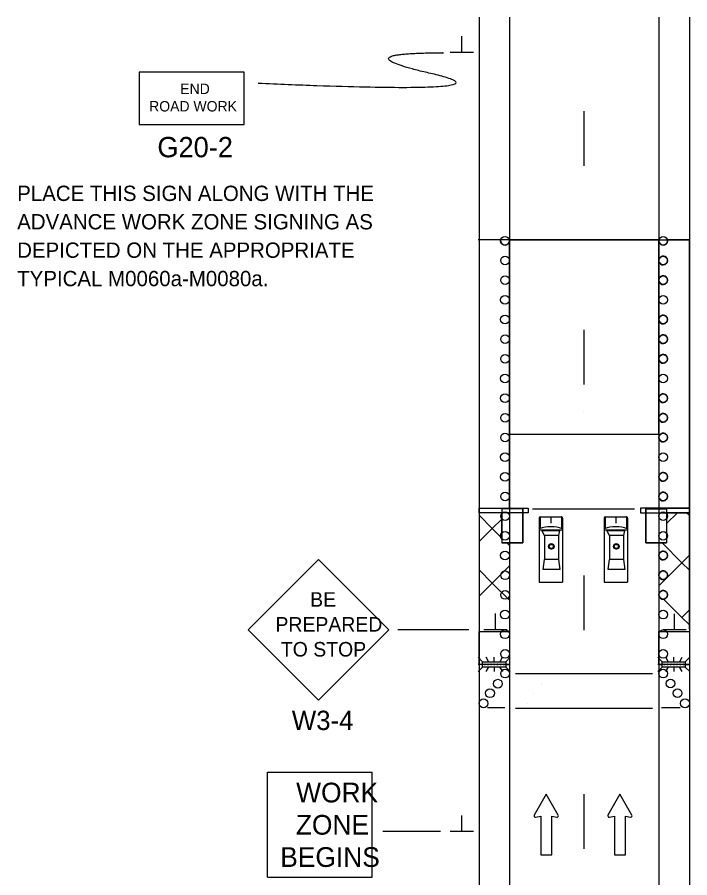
# Model space of a CAD drawing. Extents: x -1809 to 1554, y -1087 to 323.
# Drawn here: x -1702.2 to -1394.3, y -403.2 to -9.4 of the extents above; entities that cross this region are included whole.
import ezdxf

# ---------------------------------------------------------------- set-up
doc = ezdxf.new("R2010")
doc.units = 0
for name, color, linetype in [('BORDER', 7, 'Continuous'), ('BORDER_SIGNAL_WO', 7, 'Continuous'), ('Level 1', 7, 'Continuous'), ('Level 21', 7, 'Continuous'), ('Level 42', 7, 'Continuous'), ('MT_SCRATCH_LEVEL_A', 7, 'Continuous'), ('MT_SCRATCH_LEVEL_E', 7, 'Continuous'), ('MT_STAGE_1A_NOTES', 7, 'Continuous'), ('MT_STAGE_2A_NOTES', 7, 'Continuous'), ('PAVT_EDGE_EX', 7, 'Continuous'), ('PAVT_EDGE_PR', 7, 'Continuous'), ('TRAFFIC_SIGNS_PR', 7, 'Continuous'), ('TYPICAL_EX', 7, 'Continuous'), ('TYPICAL_TEXT_DIMEN_PR', 7, 'Continuous')]:
    doc.layers.add(name, color=color, linetype=linetype)

msp = doc.modelspace()

# ---------------------------------------------------------------- linework, layer by layer
at = {"layer": 'BORDER'}
msp.add_line((-1408.49, -9.43), (-1408.49, -689.95), dxfattribs=at)
at = {"layer": 'BORDER_SIGNAL_WO'}
for p, q in [((-1442.84, -52.45), (-1442.84, -77.45)), ((-1442.84, -152.45), (-1442.84, -177.45)), ((-1442.84, -264.95), (-1442.84, -289.95)), ((-1442.84, -364.95), (-1442.84, -389.95))]:
    msp.add_line(p, q, dxfattribs=at)
at = {"layer": 'Level 1'}
for p, q in [((-1463.23, -238.54), (-1463.23, -267.92)), ((-1462.87, -238.08), (-1462.73, -238.08)), ((-1462.81, -238.08), (-1453.23, -238.08)), ((-1453.23, -238.08), (-1453.09, -238.08)), ((-1453.11, -238.08), (-1453.09, -238.08)), ((-1452.6, -238.62), (-1452.6, -267.92)), ((-1433.49, -238.54), (-1433.49, -267.92)), ((-1433.13, -238.08), (-1432.99, -238.08)), ((-1433.07, -238.08), (-1423.48, -238.08)), ((-1423.48, -238.08), (-1423.34, -238.08)), ((-1423.36, -238.08), (-1423.35, -238.08)), ((-1422.85, -238.62), (-1422.85, -267.92)), ((-1462.1, -244.24), (-1453.92, -244.24)), ((-1460.87, -246.59), (-1462.1, -244.24)), ((-1454.39, -246.59), (-1460.87, -246.59)), ((-1460.87, -246.59), (-1460.87, -257.65)), ((-1453.92, -244.24), (-1454.39, -246.59)), ((-1454.39, -246.59), (-1454.39, -257.65)), ((-1432.35, -244.24), (-1424.17, -244.24)), ((-1431.13, -246.59), (-1432.35, -244.24)), ((-1424.64, -246.59), (-1431.13, -246.59)), ((-1431.13, -246.59), (-1431.13, -257.65)), ((-1424.17, -244.24), (-1424.64, -246.59)), ((-1424.64, -246.59), (-1424.64, -257.65)), ((-1461.44, -262.18), (-1460.87, -257.65)), ((-1454.39, -257.65), (-1460.87, -257.65)), ((-1454.39, -257.65), (-1453.82, -262.18)), ((-1431.69, -262.18), (-1431.13, -257.65)), ((-1424.64, -257.65), (-1431.13, -257.65)), ((-1424.64, -257.65), (-1424.08, -262.18)), ((-1453.82, -262.18), (-1461.44, -262.18)), ((-1424.08, -262.18), (-1431.69, -262.18)), ((-1463.23, -267.92), (-1452.6, -267.92)), ((-1433.49, -267.92), (-1422.85, -267.92))]:
    msp.add_line(p, q, dxfattribs=at)
at = {"layer": 'Level 21'}
msp.add_line((-1442.84, -189.95), (-1442.84, -189.95), dxfattribs=at)
at = {"layer": 'Level 42'}
for p, q in [((-1458.89, -309.8), (-1458.89, -309.8)), ((-1462.15, -314.41), (-1462.15, -314.41)), ((-1465.78, -318.79), (-1465.78, -318.79)), ((-1468.76, -323.4), (-1468.76, -323.4))]:
    msp.add_line(p, q, dxfattribs=at)
at = {"layer": 'MT_SCRATCH_LEVEL_A'}
for p, q in [((-1476.89, -9.43), (-1476.89, -689.95)), ((-1400.02, -236.15), (-1404.93, -241.06)), ((-1394.52, -237.51), (-1395.88, -236.15)), ((-1484.73, -243.37), (-1490.76, -237.33)), ((-1480.42, -239.06), (-1484.73, -243.37)), ((-1484.73, -243.37), (-1490.76, -249.4)), ((-1480.65, -247.44), (-1484.73, -243.37)), ((-1397.95, -259.08), (-1407.04, -249.99)), ((-1394.52, -255.65), (-1397.95, -259.08)), ((-1397.95, -259.08), (-1408.49, -269.63)), ((-1394.52, -262.51), (-1397.95, -259.08)), ((-1484.73, -268.37), (-1490.76, -262.33)), ((-1476.89, -260.53), (-1484.73, -268.37)), ((-1484.73, -268.37), (-1490.76, -274.4)), ((-1476.89, -276.2), (-1484.73, -268.37)), ((-1408.45, -273.58), (-1408.49, -273.54)), ((-1397.95, -284.08), (-1406.31, -275.72)), ((-1394.52, -280.65), (-1397.95, -284.08)), ((-1394.52, -287.51), (-1397.95, -284.08))]:
    msp.add_line(p, q, dxfattribs=at)
for points in [[(-1480.83, -111.25), (-1490.76, -111.25), (-1490.76, -234.05), (-1476.89, -234.05), (-1476.89, -200.29), (-1476.89, -111.25), (-1476.96, -111.25)], [(-1408.49, -111.76), (-1408.49, -111.25), (-1476.89, -111.25), (-1476.89, -200.29), (-1408.49, -200.29), (-1408.49, -192.87)], [(-1408.49, -228.88), (-1408.49, -234.05), (-1394.52, -234.05), (-1394.52, -111.25), (-1394.52, -111.25), (-1404.56, -111.25)], [(-1408.49, -120.65), (-1408.49, -111.76)], [(-1408.49, -111.76), (-1408.49, -120.65)], [(-1408.49, -129.61), (-1408.49, -120.86)], [(-1408.49, -120.86), (-1408.49, -129.61)], [(-1408.49, -147.76), (-1408.49, -129.9)], [(-1408.49, -129.9), (-1408.49, -147.76)], [(-1408.49, -156.66), (-1408.49, -147.76)], [(-1408.49, -147.76), (-1408.49, -156.66)], [(-1408.49, -165.62), (-1408.49, -156.87)], [(-1408.49, -156.87), (-1408.49, -165.62)], [(-1408.49, -183.77), (-1408.49, -165.91)], [(-1408.49, -165.91), (-1408.49, -183.77)], [(-1408.49, -192.67), (-1408.49, -183.77)], [(-1408.49, -183.77), (-1408.49, -192.67)], [(-1408.49, -192.87), (-1408.49, -200.29), (-1408.49, -201.62)], [(-1408.49, -201.92), (-1408.49, -219.78)], [(-1408.49, -219.78), (-1408.49, -228.67)]]:
    msp.add_lwpolyline(points, dxfattribs=at)
for centre, start, end in [((-1478.9, -111.76), 165.2607, 208.1824), ((-1478.9, -111.76), 208.1824, 14.7393), ((-1406.49, -111.76), 179.9985, 180.0015), ((-1406.49, -111.76), 180.0015, 208.1824), ((-1406.49, -111.76), 208.1824, 14.7241), ((-1406.5, -120.76), 177.033, 182.967), ((-1406.5, -120.76), 28.1824, 177.033), ((-1406.5, -120.76), 182.967, 208.1824), ((-1406.5, -120.76), 208.1824, 28.1824), ((-1406.5, -129.76), 175.8035, 184.1965), ((-1406.5, -129.76), 28.1824, 175.8035), ((-1406.5, -129.76), 184.1965, 208.1824), ((-1406.5, -129.76), 208.1824, 28.1824), ((-1406.49, -147.76), 28.1824, 179.9987), ((-1406.49, -147.76), 179.9987, 180.0013), ((-1406.49, -147.76), 180.0013, 208.1824), ((-1406.49, -147.76), 208.1824, 28.1824), ((-1406.5, -156.76), 177.033, 182.967), ((-1406.5, -156.76), 28.1824, 177.033), ((-1406.5, -156.76), 182.967, 208.1824), ((-1406.5, -156.76), 208.1824, 28.1824), ((-1406.5, -165.76), 28.1824, 175.8035), ((-1406.5, -165.76), 208.1824, 28.1824), ((-1406.5, -165.76), 175.8035, 184.1965), ((-1406.5, -165.76), 184.1965, 208.1824), ((-1406.49, -183.77), 28.1824, 179.9987), ((-1406.49, -183.77), 179.9987, 180.0013), ((-1406.49, -183.77), 180.0013, 208.1824), ((-1406.49, -183.77), 208.1824, 28.1824), ((-1406.5, -192.77), 177.033, 182.967), ((-1406.5, -192.77), 28.1824, 177.033), ((-1406.5, -192.77), 182.967, 208.1824), ((-1406.5, -192.77), 208.1824, 28.1824), ((-1406.5, -201.77), 28.1824, 175.8035), ((-1406.5, -201.77), 208.1824, 28.1824), ((-1406.5, -201.77), 184.1965, 208.1824), ((-1406.49, -219.78), 28.1824, 179.9991), ((-1406.49, -219.78), 180.0009, 208.1824), ((-1406.49, -219.78), 208.1824, 28.1824), ((-1406.5, -228.78), 28.1824, 177.033), ((-1406.5, -228.78), 208.1824, 28.1824), ((-1406.5, -228.78), 182.967, 208.1824)]:
    msp.add_arc(centre, 2, start, end, dxfattribs=at)
at = {"layer": 'MT_SCRATCH_LEVEL_E'}
for p, q in [((-1460.06, -364.95), (-1465.54, -374.6)), ((-1454.53, -374.6), (-1460.06, -364.95)), ((-1426.32, -364.95), (-1431.8, -374.6)), ((-1420.79, -374.6), (-1426.32, -364.95)), ((-1464.9, -375.51), (-1462.53, -375.09)), ((-1462.53, -375.09), (-1462.53, -392.77)), ((-1457.54, -392.77), (-1457.54, -375.09)), ((-1457.54, -375.09), (-1455.17, -375.51)), ((-1431.16, -375.51), (-1428.79, -375.09)), ((-1428.79, -375.09), (-1428.79, -392.77)), ((-1423.8, -392.77), (-1423.8, -375.09)), ((-1423.8, -375.09), (-1421.43, -375.51)), ((-1462.53, -392.77), (-1457.54, -392.77)), ((-1428.79, -392.77), (-1423.8, -392.77))]:
    msp.add_line(p, q, dxfattribs=at)
for centre, start, end in [((-1465, -374.9), 150.4248, 279.9638), ((-1455.08, -374.9), 260.0362, 29.7731), ((-1431.26, -374.9), 150.4248, 279.9638), ((-1421.34, -374.9), 260.0362, 29.7731)]:
    msp.add_arc(centre, 0.617, start, end, dxfattribs=at)
at = {"layer": 'MT_STAGE_1A_NOTES'}
for p, q in [((-1480.35, -234.38), (-1480.35, -249.99)), ((-1470.76, -234.38), (-1470.76, -249.99)), ((-1414.52, -234.38), (-1414.52, -249.99)), ((-1404.93, -234.38), (-1404.93, -249.99)), ((-1470.76, -249.99), (-1480.35, -249.99)), ((-1414.52, -249.99), (-1404.93, -249.99))]:
    msp.add_line(p, q, dxfattribs=at)
for points in [[(-1490.76, -234.05), (-1468.38, -234.05), (-1468.38, -236.15), (-1490.76, -236.15)], [(-1470.76, -234.38), (-1480.35, -234.38), (-1480.35, -249.99), (-1470.76, -249.99)], [(-1394.52, -234.05), (-1416.9, -234.05), (-1416.9, -236.15), (-1394.52, -236.15)], [(-1414.52, -234.38), (-1404.93, -234.38), (-1404.93, -249.99), (-1414.52, -249.99)], [(-1490.73, -305.59), (-1490.76, -290.53), (-1476.89, -290.5), (-1476.86, -305.57)], [(-1394.52, -305.59), (-1408.49, -305.59), (-1408.49, -290.5), (-1394.52, -290.5)]]:
    msp.add_lwpolyline(points, close=True, dxfattribs=at)
at = {"layer": 'MT_STAGE_2A_NOTES'}
for p, q in [((-1394.52, -236.15), (-1404.93, -236.15)), ((-1404.93, -236.15), (-1404.93, -236.54)), ((-1394.52, -289.49), (-1394.52, -236.15)), ((-1476.89, -251.2), (-1478.1, -249.99)), ((-1408.49, -273.93), (-1408.49, -289.49)), ((-1491.2, -302.33), (-1489.3, -304.23)), ((-1486.43, -304.23), (-1487.53, -302.33)), ((-1483.87, -304.23), (-1483.87, -302.33)), ((-1481.09, -304.23), (-1479.99, -302.33)), ((-1478.43, -304.23), (-1476.53, -302.33)), ((-1489.3, -305.59), (-1491.2, -305.59)), ((-1491.2, -308.85), (-1489.3, -306.96)), ((-1488.2, -305.59), (-1488.2, -305.59)), ((-1487.54, -308.86), (-1486.45, -306.96)), ((-1486.74, -305.59), (-1486.74, -305.59)), ((-1485.28, -305.59), (-1485.28, -305.59)), ((-1483.87, -306.96), (-1483.87, -308.86)), ((-1483.82, -305.59), (-1483.82, -305.59)), ((-1482.36, -305.59), (-1482.36, -305.59)), ((-1479.97, -308.86), (-1481.07, -306.96)), ((-1480.89, -305.59), (-1480.89, -305.59)), ((-1479.43, -305.59), (-1479.43, -305.59)), ((-1478.43, -305.59), (-1476.53, -305.59)), ((-1478.43, -306.96), (-1476.53, -308.86)), ((-1408.49, -305.59), (-1407.1, -305.59)), ((-1407.1, -305.59), (-1406.94, -305.59)), ((-1406.94, -305.59), (-1406.94, -304.38)), ((-1396.38, -304.38), (-1396.38, -305.59)), ((-1396.38, -305.59), (-1396.23, -305.59)), ((-1396.23, -305.59), (-1394.52, -305.59))]:
    msp.add_line(p, q, dxfattribs=at)
for points in [[(-1480.35, -245.41), (-1480.35, -239.15)], [(-1404.93, -239.01), (-1404.93, -245.54)], [(-1404.93, -248.03), (-1404.93, -249.99), (-1408.49, -249.99), (-1408.49, -255.78)], [(-1408.49, -255.78), (-1408.49, -264.68)], [(-1408.49, -264.89), (-1408.49, -273.64)]]:
    msp.add_lwpolyline(points, dxfattribs=at)
msp.add_lwpolyline([(-1478.59, -306.8), (-1489.15, -306.8), (-1489.15, -304.38), (-1478.59, -304.38)], close=True, dxfattribs=at)
for centre in [(-1488.19, -305.59), (-1486.74, -305.59), (-1485.28, -305.59), (-1483.82, -305.59), (-1482.36, -305.59), (-1480.89, -305.59), (-1479.43, -305.59)]:
    msp.add_circle(centre, 0.255, dxfattribs=at)
for centre, start, end in [((-1478.89, -237.78), 136.8734, 208.1824), ((-1478.89, -237.78), 208.1824, 223.1266), ((-1406.5, -237.78), 28.1824, 38.2173), ((-1406.5, -237.78), 321.7827, 28.1824), ((-1478.9, -246.78), 136.7611, 208.1824), ((-1478.9, -246.78), 208.1824, 223.2389), ((-1406.49, -246.78), 321.5351, 38.4649), ((-1406.49, -255.78), 28.1824, 180), ((-1406.49, -255.78), 180, 208.1824), ((-1406.49, -255.78), 208.1824, 28.1824), ((-1406.5, -264.78), 28.1824, 177.033), ((-1406.5, -264.78), 208.1824, 28.1824), ((-1406.5, -264.78), 182.967, 208.1824), ((-1406.5, -273.78), 28.1824, 175.8035), ((-1406.5, -273.78), 184.1965, 208.1824), ((-1406.5, -273.78), 208.1824, 28.1824)]:
    msp.add_arc(centre, 2, start, end, dxfattribs=at)
at = {"layer": 'PAVT_EDGE_EX'}
for p, q in [((-1490.76, -9.43), (-1490.76, -690.07)), ((-1394.52, -9.43), (-1394.52, -689.95))]:
    msp.add_line(p, q, dxfattribs=at)
at = {"layer": 'PAVT_EDGE_PR'}
for p, q in [((-1476.89, -111.25), (-1491.22, -111.25)), ((-1462.8, -238.08), (-1462.8, -243.41)), ((-1457.91, -238.08), (-1457.93, -240.95)), ((-1453.09, -238.08), (-1453.09, -243.38)), ((-1433.06, -238.08), (-1433.06, -243.41)), ((-1428.17, -238.08), (-1428.19, -240.95)), ((-1423.34, -238.08), (-1423.34, -243.38)), ((-1463.23, -243.94), (-1452.62, -243.94)), ((-1433.49, -243.94), (-1422.88, -243.94))]:
    msp.add_line(p, q, dxfattribs=at)
for centre, radius in [((-1457.71, -251.59), 1.27), ((-1457.7, -251.59), 1.2), ((-1457.72, -251.59), 0.93), ((-1427.97, -251.59), 1.27), ((-1427.95, -251.59), 1.2), ((-1427.98, -251.59), 0.93)]:
    msp.add_circle(centre, radius, dxfattribs=at)
for centre, radius, start, end in [((-1462.76, -238.53), 0.469, 104.046, 184.9392), ((-1453.06, -238.55), 0.469, 350.5905, 93.3544), ((-1433.01, -238.53), 0.469, 104.046, 184.9392), ((-1423.32, -238.55), 0.469, 350.5905, 93.3544), ((-1457.88, -258.19), 15.57, 70.1557, 110.0625), ((-1428.14, -258.19), 15.57, 70.1557, 110.0625)]:
    msp.add_arc(centre, radius, start, end, dxfattribs=at)
at = {"layer": 'TRAFFIC_SIGNS_PR'}
for p, q in [((-1564.28, -257.54), (-1596.52, -289.78)), ((-1532.04, -289.78), (-1564.28, -257.54)), ((-1596.52, -289.78), (-1564.28, -322.02)), ((-1564.28, -322.02), (-1532.04, -289.78)), ((-1409, -302.33), (-1407.1, -304.23)), ((-1404.23, -304.23), (-1405.32, -302.33)), ((-1401.66, -304.23), (-1401.66, -302.33)), ((-1398.88, -304.23), (-1397.79, -302.33)), ((-1396.23, -304.23), (-1394.33, -302.33)), ((-1407.1, -305.59), (-1409, -305.59)), ((-1409, -308.85), (-1407.1, -306.96)), ((-1406, -305.59), (-1406, -305.59)), ((-1405.34, -308.86), (-1404.25, -306.96)), ((-1404.54, -305.59), (-1404.54, -305.59)), ((-1403.08, -305.59), (-1403.08, -305.59)), ((-1401.66, -306.96), (-1401.66, -308.86)), ((-1401.61, -305.59), (-1401.61, -305.59)), ((-1400.15, -305.59), (-1400.15, -305.59)), ((-1397.77, -308.86), (-1398.87, -306.96)), ((-1398.69, -305.59), (-1398.69, -305.59)), ((-1397.23, -305.59), (-1397.23, -305.59)), ((-1396.23, -305.59), (-1394.33, -305.59)), ((-1396.23, -306.96), (-1394.33, -308.86)), ((-1587.64, -402.93), (-1587.64, -354.93)), ((-1587.64, -354.93), (-1539.64, -354.93)), ((-1539.64, -402.93), (-1539.64, -354.93)), ((-1587.64, -402.93), (-1539.64, -402.93))]:
    msp.add_line(p, q, dxfattribs=at)
for points in [[(-1646.3, -58.5), (-1598.3, -58.5), (-1598.3, -34.5), (-1646.3, -34.5)], [(-1396.38, -306.8), (-1406.94, -306.8), (-1406.94, -304.38), (-1396.38, -304.38)]]:
    msp.add_lwpolyline(points, close=True, dxfattribs=at)
for centre, radius in [((-1478.9, -111.76), 2), ((-1406.49, -111.76), 2), ((-1478.89, -120.76), 2), ((-1406.5, -120.76), 2), ((-1478.89, -129.76), 2), ((-1406.5, -129.76), 2), ((-1478.9, -138.76), 2), ((-1406.49, -138.76), 2), ((-1478.9, -147.76), 2), ((-1406.49, -147.76), 2), ((-1478.89, -156.77), 2), ((-1406.5, -156.76), 2), ((-1478.89, -165.77), 2), ((-1406.5, -165.76), 2), ((-1478.9, -174.77), 2), ((-1406.49, -174.77), 2), ((-1478.9, -183.77), 2), ((-1406.49, -183.77), 2), ((-1478.89, -192.78), 2), ((-1406.5, -192.77), 2), ((-1478.89, -201.78), 2), ((-1406.5, -201.77), 2), ((-1478.9, -210.78), 2), ((-1406.49, -210.78), 2), ((-1478.9, -219.78), 2), ((-1406.49, -219.78), 2), ((-1478.89, -228.78), 2), ((-1406.5, -228.78), 2), ((-1478.89, -237.78), 2), ((-1406.5, -237.78), 2), ((-1478.9, -246.78), 2), ((-1406.49, -246.78), 2), ((-1478.9, -255.78), 2), ((-1406.49, -255.78), 2), ((-1478.89, -264.79), 2), ((-1406.5, -264.78), 2), ((-1478.89, -273.79), 2), ((-1406.5, -273.78), 2), ((-1478.9, -282.79), 2), ((-1406.49, -282.79), 2), ((-1478.9, -291.79), 2), ((-1406.49, -291.79), 2), ((-1478.89, -300.8), 2), ((-1406.5, -300.79), 2), ((-1405.99, -305.59), 0.255), ((-1404.54, -305.59), 0.255), ((-1403.08, -305.59), 0.255), ((-1401.61, -305.59), 0.255), ((-1400.15, -305.59), 0.255), ((-1398.69, -305.59), 0.255), ((-1397.23, -305.59), 0.255), ((-1478.89, -309.8), 2), ((-1406.5, -309.79), 2), ((-1406.49, -309.8), 2), ((-1482.15, -314.41), 2), ((-1403.19, -314.32), 2), ((-1485.78, -318.79), 2), ((-1399.92, -318.76), 2), ((-1488.76, -323.4), 2), ((-1396.52, -323.4), 2)]:
    msp.add_circle(centre, radius, dxfattribs=at)
at = {"layer": 'TYPICAL_EX'}
for p, q in [((-1498.63, -25.55), (-1498.63, -18.16)), ((-1498.63, -25.55), (-1503.97, -25.55)), ((-1493.28, -25.55), (-1498.63, -25.55)), ((-1408.47, -111.25), (-1394.52, -111.25)), ((-1483.33, -289.75), (-1483.33, -282.36)), ((-1401.4, -289.77), (-1401.4, -282.38)), ((-1483.33, -289.75), (-1488.67, -289.75)), ((-1477.99, -289.75), (-1483.33, -289.75)), ((-1401.4, -289.77), (-1406.74, -289.77)), ((-1396.05, -289.77), (-1401.4, -289.77)), ((-1498.63, -382.09), (-1498.63, -374.69)), ((-1498.63, -382.09), (-1503.97, -382.09)), ((-1493.28, -382.09), (-1498.63, -382.09))]:
    msp.add_line(p, q, dxfattribs=at)
at = {"layer": 'TYPICAL_TEXT_DIMEN_PR'}
for p, q in [((-1507.35, -25.71), (-1507.58, -25.72)), ((-1507.58, -25.72), (-1507.09, -25.72)), ((-1476.89, -111.25), (-1408.49, -111.25)), ((-1476.89, -200.29), (-1408.49, -200.29)), ((-1466.29, -234.38), (-1419.69, -234.38)), ((-1495.4, -289.75), (-1528, -289.75)), ((-1474.13, -309.8), (-1411.44, -309.8)), ((-1478.93, -325.4), (-1486.88, -325.4)), ((-1474.13, -325.54), (-1411.44, -325.54)), ((-1398.8, -325.4), (-1407.22, -325.4)), ((-1508.43, -382.09), (-1534.83, -382.09))]:
    msp.add_line(p, q, dxfattribs=at)
msp.add_open_spline([(-1591.84, -39.6), (-1469.94, -44.97), (-1554.48, -25.71), (-1507.35, -25.71)], degree=2, dxfattribs=at)

# ---------------------------------------------------------------- texts
at = {"layer": 'TRAFFIC_SIGNS_PR'}
for s, height, p in [('END', 4.789, (-1627.55, -44.59)), ('ROAD WORK', 4.789, (-1641.79, -52.57)), ('G20-2', 9.3, (-1638.01, -73.52)), ('PLACE THIS SIGN ALONG WITH THE', 7, (-1702.19, -93.52)), ('ADVANCE WORK ZONE SIGNING AS', 7, (-1702.19, -106.52)), ('DEPICTED ON THE APPROPRIATE', 7, (-1702.19, -119.52)), ('TYPICAL M0060a-M0080a.', 7, (-1702.19, -132.52)), ('BE', 6.65, (-1568.1, -279.18)), ('PREPARED', 6.65, (-1583.98, -290.58)), ('TO STOP', 6.65, (-1581.5, -301.98)), ('W3-4', 8.835, (-1576.48, -335.61)), ('WORK', 9.021, (-1574.49, -368.73)), ('ZONE', 9.021, (-1574.64, -383.49)), ('BEGINS', 9.021, (-1581.79, -398.25))]:
    msp.add_text(s, height=height, dxfattribs=at).set_placement(p)

doc.saveas('drawing.dxf')
